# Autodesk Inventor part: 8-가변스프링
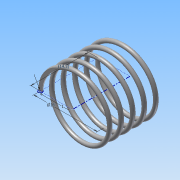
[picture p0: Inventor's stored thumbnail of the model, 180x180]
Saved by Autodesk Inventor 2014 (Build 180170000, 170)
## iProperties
Created: 2015-06
Part Number: 8-가변스프링
Material: 강철, 연강
Document SubType Name: Modeling
Designer: Administrator
Density: 7.86 g/cm^3
Appearance: 강철
Mass: 1.52996 g
Surface Area: 7.87153 cm^2
Volume: 0.194652 cm^3
Author: Administrator
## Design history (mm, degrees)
sketch "스케치1"
  geometry: L1 (0, 0)-(-8, 0); L2 (-8, 0)-(-8, 14.5); L3 (-8, 14.5)-(0, 14.5); L4 (0, 14.5)-(0, 0); C1 r 0.5 at (-8, 0)
  constraints: 8 end point, 2 parallel, 1 centre point, 1 coincident, 1 horizontal, 1 perpendicular
  dimensions: "d0" = 1 diameter of C1; "d1" = 16 diameter of L2 L4; "d2" = 14.5 distance of L1.end L2.end (derived)
feature "코일1" sketch "스케치1" pitch "d3" = 10; turns "d5" = 5; dims "d4" = 14.5 (= d2), "d6" = 0, angle "d7" = 90 deg, angle "d8" = 90 deg, "d9" = 0, "d10" = 0
sketch "스케치2"
  geometry: L1 (8.5, 0)-(7.5, 0) reference; 1 further point
  constraints: 1 horizontal alignment
extrude "돌출1" cut sketch "스케치2" stored distance "d11" = 10; taper "d12" = 0 deg
node "작업 평면1"
sketch "스케치3"
  geometry: L1 (7.5, 0)-(8.5, 0) reference; 1 further point
  constraints: 1 horizontal alignment
extrude "돌출2" cut sketch "스케치3" stored distance "d14" = 10; taper "d15" = 0 deg
node "솔리드1"
node "절단 모서리 투영1"
node "절단 모서리 투영2"
other parameters: "d13" = 14.5 (= d2)
